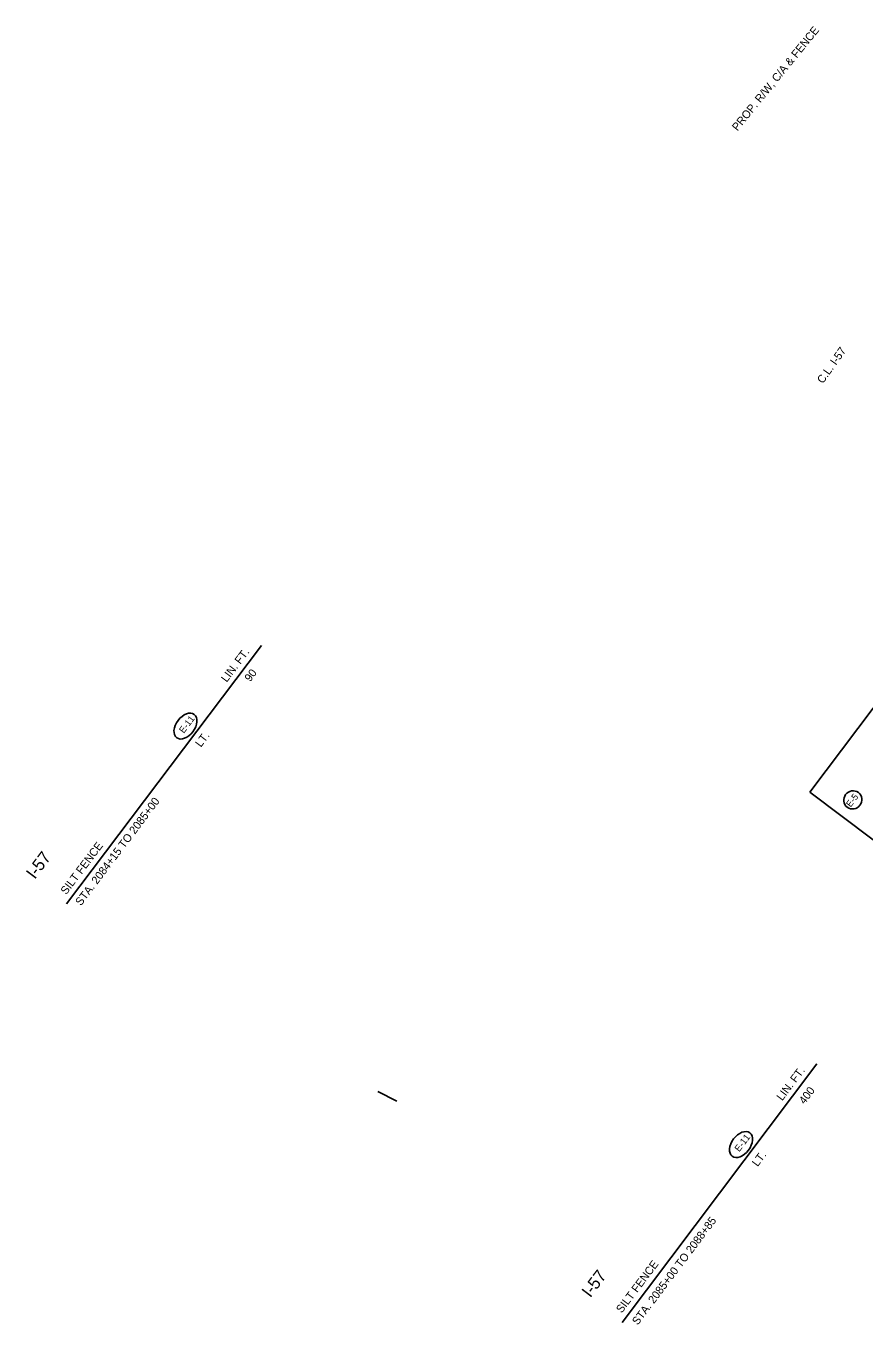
# Model space of a CAD drawing. Extents: x 1713751 to 1715480, y 763628 to 765350.
# Drawn here: x 1713751 to 1714378, y 763785 to 764759 of the extents above; entities that cross this region are included whole.
import ezdxf

# ---------------------------------------------------------------- set-up
doc = ezdxf.new("R2010")
doc.units = 0
for name, color, linetype in [('1', 7, 'Continuous'), ('44', 7, 'Continuous'), ('Default', 7, 'Continuous'), ('Level 1', 7, 'Continuous'), ('Level 44', 7, 'Continuous'), ('R_Draft', 7, 'Continuous')]:
    doc.layers.add(name, color=color, linetype=linetype)

msp = doc.modelspace()

# ---------------------------------------------------------------- linework, layer by layer
at = {"layer": '1'}
msp.add_lwpolyline([(1714337.84, 764184.32), (1714576.55, 764501.1), (1714694.66, 764412.1), (1714455.95, 764095.31)], close=True, dxfattribs=at)
for centre in [(1713870.11, 764233.83), (1714286.32, 763920.19)]:
    msp.add_ellipse(centre, major_axis=(6.59, 8.75), ratio=0.638788, dxfattribs=at)
at = {"layer": '44'}
for p, q in [((1713781.07, 764100.59), (1713927.01, 764294.25)), ((1714197.28, 763786.94), (1714343.22, 763980.61))]:
    msp.add_line(p, q, dxfattribs=at)
at = {"layer": 'Default'}
msp.add_line((1714014.11, 763959.96), (1714028.37, 763952.71), dxfattribs=at)
at = {"layer": 'Level 1'}
msp.add_ellipse((1714370.09, 764178.51), major_axis=(-4.14, -5.5), ratio=0.97521, dxfattribs=at)

# ---------------------------------------------------------------- texts
at = {"layer": '1'}
for p in [(1713868.81, 764228.03), (1714285.03, 763914.38)]:
    msp.add_text('E-11', height=4.999, rotation=53, dxfattribs=at).set_placement(p)
at = {"layer": '44'}
for s, p in [('LIN. FT.', (1713900.99, 764266.23)), ('90', (1713918.58, 764266.6)), ('LT.', (1713881.61, 764217.53)), ('STA. 2084+15 TO 2085+00', (1713791.79, 764098.76)), ('SILT FENCE      ', (1713780.75, 764107.08)), ('LIN. FT.', (1714317.2, 763952.58)), ('400', (1714333.94, 763949.94)), ('LT.', (1714298.73, 763903.21)), ('STA. 2085+00 TO 2088+85', (1714208.91, 763784.43)), ('SILT FENCE      ', (1714196.96, 763793.44))]:
    msp.add_text(s, height=6, rotation=53, dxfattribs=at).set_placement(p)
at = {"layer": 'Level 1'}
msp.add_text('E-5 ', height=4.876, rotation=53.058, dxfattribs=at).set_placement((1714368.48, 764172.67))
at = {"layer": 'Level 44'}
for p in [(1713757.23, 764118.54), (1714173.45, 763804.9)]:
    msp.add_text('I-57', height=9.143, rotation=53.00001, dxfattribs=at).set_placement(p)
at = {"layer": 'R_Draft'}
for s, rotation, p in [('PROP. R/W, C/A & FENCE', 50.89014, (1714283.64, 764679.43)), ('C.L. I-57', 54.64067, (1714347.64, 764490.06))]:
    msp.add_text(s, height=6, rotation=rotation, dxfattribs=at).set_placement(p)

doc.saveas('drawing.dxf')
